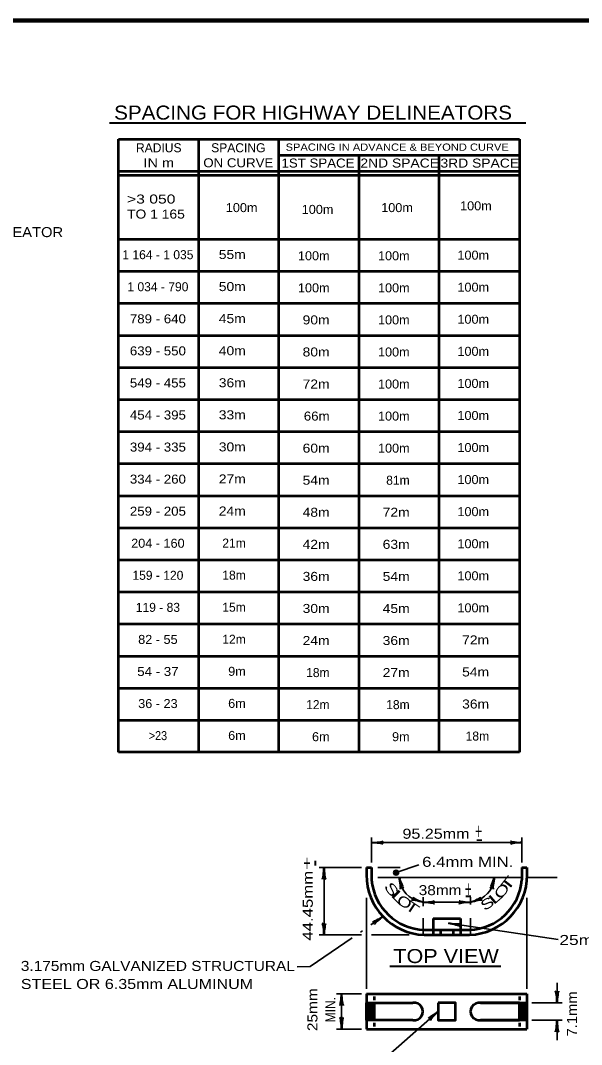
# Model space of a CAD drawing. Extents: x -89 to 766, y -60 to 484.
# Drawn here: x 393.7 to 561.6, y 171.5 to 478.1 of the extents above; entities that cross this region are included whole.
import ezdxf
from ezdxf.enums import TextEntityAlignment as Align

# ---------------------------------------------------------------- set-up
doc = ezdxf.new("R2010")
doc.units = 0
doc.header["$LTSCALE"] = 1.1
doc.linetypes.add('MEDIUM_DASHED', pattern=[4.5, 3, -1.5])
doc.layers.add('1', color=7, linetype='Continuous', lineweight=35)

msp = doc.modelspace()

# ---------------------------------------------------------------- hatches: boundary and pattern name
at = {"layer": '1'}
msp.add_hatch(color=256, dxfattribs=at).paths.add_polyline_path([(506.875, 222.927, 1), (505.375, 222.927, 1)])

# ---------------------------------------------------------------- linework, layer by layer
at = {"layer": '1', "lineweight": 40}
for p, q in [((420.336, 447.477), (545.003, 447.477)), ((504.235, 194.956), (537.477, 194.956))]:
    msp.add_line(p, q, dxfattribs=at)
at = {"layer": '1', "lineweight": 53}
for p, q in [((423.047, 258.995), (423.047, 442.595)), ((423.047, 442.595), (543.047, 442.595)), ((447.047, 258.995), (447.047, 442.595)), ((471.047, 258.995), (471.047, 442.595)), ((543.047, 442.595), (543.047, 258.995)), ((471.047, 437.795), (543.047, 437.795)), ((495.047, 258.995), (495.047, 437.795)), ((519.047, 258.995), (519.047, 437.795)), ((423.047, 432.995), (543.047, 432.995)), ((423.047, 431.795), (543.047, 431.795)), ((423.047, 412.595), (543.047, 412.595)), ((423.047, 402.995), (543.047, 402.995)), ((423.047, 393.395), (543.047, 393.395)), ((423.047, 383.795), (543.047, 383.795)), ((423.047, 374.195), (543.047, 374.195)), ((423.047, 364.595), (543.047, 364.595)), ((423.047, 354.995), (543.047, 354.995)), ((423.047, 345.395), (543.047, 345.395)), ((423.047, 335.795), (543.047, 335.795)), ((423.047, 326.195), (543.047, 326.195)), ((423.047, 316.595), (543.047, 316.595)), ((423.047, 306.995), (543.047, 306.995)), ((423.047, 297.395), (543.047, 297.395)), ((423.047, 287.795), (543.047, 287.795)), ((423.047, 278.195), (543.047, 278.195)), ((423.047, 268.595), (543.047, 268.595)), ((543.047, 258.995), (423.047, 258.995)), ((497.317, 224.421), (497.317, 222.294)), ((497.317, 224.421), (498.817, 224.421)), ((498.817, 224.421), (498.817, 220.794)), ((543.817, 224.421), (543.817, 220.794)), ((543.817, 224.421), (545.317, 224.421)), ((545.317, 224.421), (545.317, 222.294)), ((517.192, 209.169), (517.192, 204.294)), ((517.192, 209.169), (525.442, 209.169)), ((525.442, 209.169), (525.442, 204.294)), ((514.567, 205.794), (528.067, 205.794)), ((514.567, 204.294), (528.067, 204.294)), ((497.317, 186.593), (545.317, 186.593)), ((497.317, 186.593), (497.317, 183.968)), ((499.567, 185.843), (499.567, 184.718)), ((543.067, 185.843), (543.067, 184.718)), ((545.317, 186.593), (545.317, 183.968)), ((497.317, 183.546), (497.738, 183.968)), ((497.317, 182.485), (498.799, 183.968)), ((497.317, 181.425), (499.567, 183.675)), ((497.317, 180.364), (499.567, 182.614)), ((497.317, 179.303), (499.567, 181.553)), ((499.567, 183.968), (499.567, 178.718)), ((499.567, 183.968), (511.192, 183.968)), ((499.567, 183.968), (499.567, 178.718)), ((543.067, 178.718), (543.067, 183.968)), ((543.067, 183.968), (543.067, 178.718)), ((545.317, 181.345), (543.067, 183.595)), ((545.317, 180.284), (543.067, 182.534)), ((545.317, 179.223), (543.067, 181.473)), ((545.317, 182.405), (543.754, 183.968)), ((545.317, 183.466), (544.815, 183.968)), ((497.317, 178.718), (497.317, 176.093)), ((511.192, 178.718), (497.317, 178.718)), ((497.792, 178.718), (499.567, 180.493)), ((498.852, 178.718), (499.567, 179.432)), ((499.567, 177.968), (499.567, 176.843)), ((544.762, 178.718), (543.067, 180.413)), ((543.701, 178.718), (543.067, 179.352)), ((543.067, 177.968), (543.067, 176.843)), ((545.317, 178.718), (545.317, 176.093)), ((497.317, 176.093), (545.317, 176.093))]:
    msp.add_line(p, q, dxfattribs=at)
at = {"layer": '1'}
for p, q in [((498.817, 225.921), (498.817, 233.421)), ((543.817, 225.921), (543.817, 233.421)), ((498.817, 231.921), (543.817, 231.921)), ((495.817, 224.421), (483.067, 224.421)), ((484.567, 224.421), (484.567, 204.294)), ((500.692, 224.468), (507.357, 224.468)), ((506.126, 222.927), (512.985, 225.24)), ((500.692, 221.468), (543.817, 221.468)), ((545.359, 221.468), (554.359, 221.468)), ((497.317, 215.421), (497.317, 188.093)), ((514.192, 215.544), (514.192, 212.889)), ((528.442, 215.544), (528.442, 213.382)), ((545.317, 215.421), (545.317, 188.093)), ((514.192, 214.044), (528.442, 214.044)), ((502.225, 209.781), (498.552, 207.251)), ((514.192, 209.258), (514.192, 206.169)), ((528.442, 209.258), (528.442, 206.169)), ((496.081, 205.549), (495.493, 205.144)), ((521.85, 207.763), (554.609, 202.879)), ((493.023, 203.443), (480.455, 194.787)), ((495.817, 204.294), (483.067, 204.294)), ((510.067, 204.294), (498.817, 204.294)), ((514.192, 205.419), (514.192, 204.669)), ((528.442, 205.419), (528.442, 204.669)), ((480.455, 194.787), (476.517, 194.736)), ((554.317, 189.968), (554.317, 183.968)), ((495.817, 186.593), (488.317, 186.593)), ((489.817, 186.593), (489.817, 176.093)), ((546.817, 183.968), (555.817, 183.968)), ((546.817, 178.718), (555.817, 178.718)), ((554.317, 178.718), (554.317, 172.718)), ((495.817, 176.093), (488.317, 176.093))]:
    msp.add_line(p, q, dxfattribs=at)
at = {"layer": '1', "linetype": 'MEDIUM_DASHED', "lineweight": 53}
for p, q in [((519.442, 205.794), (519.442, 204.294)), ((523.192, 205.794), (523.192, 204.294))]:
    msp.add_line(p, q, dxfattribs=at)
at = {"layer": '1', "lineweight": 158}
msp.add_lwpolyline([(759.817, 478.083), (-31.883, 477.983), (-31.783, -48.017)], dxfattribs=at)
at = {"layer": '1'}
msp.add_lwpolyline([(518.692, 181.343), (504.481, 168.773), (493.885, 168.773)], dxfattribs=at)
at = {"layer": '1', "lineweight": 53}
for points in [[(497.317, 178.718), (497.317, 183.968), (511.192, 183.968)], [(511.192, 178.718), (499.567, 178.718), (499.567, 183.968)], [(531.442, 183.968), (545.317, 183.968), (545.317, 178.718), (531.442, 178.718)], [(531.442, 178.718), (543.067, 178.718), (543.067, 183.968), (531.442, 183.968)]]:
    msp.add_lwpolyline(points, dxfattribs=at)
msp.add_lwpolyline([(518.692, 183.968), (518.692, 178.718), (523.942, 178.718), (523.942, 183.968)], close=True, dxfattribs=at)
at = {"layer": '1'}
msp.add_circle((506.125, 222.927), 0.75, dxfattribs=at)
at = {"layer": '1', "lineweight": 53}
for centre, radius, start, end in [((515.106, 222.129), 17.844, 179.46942, 268.10829), ((515.106, 222.129), 16.344, 184.68607, 268.10829), ((527.527, 222.129), 16.344, 271.89171, 355.31393), ((527.527, 222.129), 17.844, 271.89171, 0.53058), ((511.543, 181.343), 2.648, 262.37185, 97.62815), ((511.543, 181.343), 2.648, 262.37185, 97.62815), ((531.09, 181.343), 2.648, 82.37185, 277.62815), ((531.09, 181.343), 2.648, 82.37185, 277.62815)]:
    msp.add_arc(centre, radius, start, end, dxfattribs=at)
at = {"layer": '1'}
for centre, start, end in [((515.106, 222.129), 198.64913, 263.51251), ((527.527, 222.129), 276.48749, 341.85662)]:
    msp.add_arc(centre, 8.094, start, end, dxfattribs=at)
at = {"layer": '1', "lineweight": 40}
for centre, major_axis, ratio, start_param, end_param in [((500.161, 231.667), (-2.108, 0.211), 0.07063, 3.1407148, 5.41811), ((500.126, 232.253), (-2.143, -0.187), 0.122415, 0.8963533, 3.1415927), ((542.507, 231.59), (2.143, 0.187), 0.122415, 0.8963533, 3.1415927), ((542.507, 231.59), (2.143, 0.187), 0.122415, 0.8963533, 3.1415927), ((542.472, 232.175), (2.108, -0.211), 0.07063, 3.1407148, 5.41811), ((542.472, 232.175), (2.108, -0.211), 0.07063, 3.1407148, 5.41811), ((484.313, 223.077), (0.211, 2.108), 0.07063, 3.1407148, 5.41811), ((484.313, 223.077), (0.211, 2.108), 0.07063, 3.1407148, 5.41811), ((484.898, 223.112), (-0.187, 2.143), 0.122415, 0.8963533, 3.1415927), ((484.898, 223.112), (-0.187, 2.143), 0.122415, 0.8963533, 3.1415927), ((507.062, 220.109), (-0.362, 2.12), 0.122415, 3.1415927, 5.386832), ((507.638, 220.223), (0.738, -1.985), 0.07063, 4.006668, 6.2840632), ((534.996, 220.223), (-0.738, -1.985), 0.07063, 6.2823074, 8.5597026), ((535.571, 220.109), (0.362, 2.12), 0.122415, 0.8963533, 3.1415927), ((512.821, 214.25), (2.071, -0.443), 0.07063, 0.8650754, 3.1424706), ((513.033, 214.796), (1.983, -0.833), 0.122415, 3.1415927, 5.386832), ((529.6, 214.796), (-1.983, -0.833), 0.122415, 0.8963533, 3.1415927), ((529.813, 214.25), (-2.071, -0.443), 0.07063, 3.1407148, 5.41811), ((515.536, 213.79), (-2.108, 0.211), 0.07063, 3.1407148, 5.41811), ((515.536, 213.79), (-2.108, 0.211), 0.07063, 3.1407148, 5.41811), ((515.501, 214.375), (-2.143, -0.187), 0.122415, 0.8963533, 3.1415927), ((515.501, 214.375), (-2.143, -0.187), 0.122415, 0.8963533, 3.1415927), ((527.132, 213.712), (2.143, 0.187), 0.122415, 0.8963533, 3.1415927), ((527.132, 213.712), (2.143, 0.187), 0.122415, 0.8963533, 3.1415927), ((527.097, 214.298), (2.108, -0.211), 0.07063, 3.1407148, 5.41811), ((527.097, 214.298), (2.108, -0.211), 0.07063, 3.1407148, 5.41811), ((500.973, 209.227), (1.855, 1.022), 0.07063, 3.1407148, 5.41811), ((500.973, 209.227), (1.855, 1.022), 0.07063, 3.1407148, 5.41811), ((501.334, 208.765), (1.658, 1.37), 0.122415, 0.8963533, 3.1415927), ((501.334, 208.765), (1.658, 1.37), 0.122415, 0.8963533, 3.1415927), ((484.235, 205.603), (0.187, -2.143), 0.122415, 0.8963533, 3.1415927), ((484.235, 205.603), (0.187, -2.143), 0.122415, 0.8963533, 3.1415927), ((484.821, 205.638), (-0.211, -2.108), 0.07063, 3.1407148, 5.41811), ((484.821, 205.638), (-0.211, -2.108), 0.07063, 3.1407148, 5.41811), ((523.143, 207.314), (-2.054, 0.519), 0.07063, 3.1407148, 5.41811), ((523.194, 207.898), (-2.147, 0.131), 0.122415, 0.8963533, 3.1415927), ((553.985, 185.277), (0.187, -2.143), 0.122415, 0.8963533, 3.1415927), ((554.571, 185.312), (-0.211, -2.108), 0.07063, 3.1407148, 5.41811), ((489.563, 185.248), (0.211, 2.108), 0.07063, 3.1407148, 5.41811), ((489.563, 185.248), (0.211, 2.108), 0.07063, 3.1407148, 5.41811), ((490.148, 185.283), (-0.187, 2.143), 0.122415, 0.8963533, 3.1415927), ((490.148, 185.283), (-0.187, 2.143), 0.122415, 0.8963533, 3.1415927), ((517.516, 180.642), (-1.718, -1.239), 0.07063, 6.2823074, 8.5597026), ((517.516, 180.642), (-1.718, -1.239), 0.07063, 6.2823074, 8.5597026), ((517.931, 180.227), (1.481, 1.56), 0.122415, 0.8963533, 3.1415927), ((517.931, 180.227), (1.481, 1.56), 0.122415, 0.8963533, 3.1415927), ((489.485, 177.402), (0.187, -2.143), 0.122415, 0.8963533, 3.1415927), ((490.071, 177.437), (-0.211, -2.108), 0.07063, 3.1407148, 5.41811), ((554.063, 177.373), (0.211, 2.108), 0.07063, 3.1407148, 5.41811), ((554.648, 177.408), (-0.187, 2.143), 0.122415, 0.8963533, 3.1415927)]:
    msp.add_ellipse(centre, major_axis=major_axis, ratio=ratio, start_param=start_param, end_param=end_param, dxfattribs=at)

# ---------------------------------------------------------------- texts
at = {"layer": '1'}
for s, height, width, p in [('SPACING FOR HIGHWAY DELINEATORS', 4.2, 1.1, (421.724, 448.403)), ('SPACING IN ADVANCE & BEYOND CURVE', 2.16, 1.15, (473.057, 439.084)), ('1ST SPACE', 2.7, 1.1, (471.826, 434.051)), ('2ND SPACE', 2.7, 1.15, (495.441, 434.051)), ('3RD SPACE', 2.7, 1.15, (519.418, 434.036)), ('>3 050', 2.7, 1.3, (425.582, 423.27)), ('100m', 2.7, 1.05, (455.159, 420.706)), ('100m', 2.7, 1.05, (501.679, 420.706)), ('100m', 2.7, 1.05, (525.294, 421.238)), ('TO 1 165', 2.7, 1.15, (425.582, 418.77)), ('100m', 2.7, 1.05, (477.886, 420.173)), ('HOUSED DELINEATOR', 3, 1.1, (358.152, 413.22)), ('95.25mm', 3, 1.2, (508.048, 233.078)), ('+', 4.8, 0.55, (529.826, 232.976)), ('+', 4.8, 0.55, (478.435, 223.433)), ('6.4mm MIN.', 3, 1.25, (513.94, 224.667)), ('38mm', 3, 1.15, (512.904, 216.188)), ('+', 4.8, 0.55, (526.72, 215.666)), ('25mm FLAT', 3, 1.3, (555.001, 201.268)), ('TOP VIEW', 4.2, 1.15, (505.31, 195.853)), ('3.175mm GALVANIZED STRUCTURAL', 3, 1.15, (393.792, 193.494)), ('STEEL OR 6.35mm ALUMINUM', 3, 1.2, (393.792, 188.094))]:
    msp.add_text(s, height=height, dxfattribs=dict(at, width=width)).set_placement(p)
for s, p in [('RADIUS', (435.081, 438.627)), ('SPACING', (458.897, 438.627)), ('1 164 - 1 035', (434.825, 406.606)), ('1 034 - 790', (434.825, 397.006)), ('159 - 120', (434.825, 310.606)), ('119 - 83', (434.825, 301.006))]:
    msp.add_text(s, height=2.7, dxfattribs=at).set_placement(p, align=Align.CENTER)
for s, width, p in [('IN m', 1.2, (435.081, 434.127)), ('ON CURVE', 1.1, (458.897, 434.127)), ('789 - 640', 1.1, (434.825, 387.406)), ('639 - 550', 1.1, (434.825, 377.805)), ('549 - 455', 1.1, (434.825, 368.206)), ('454 - 395', 1.1, (434.825, 358.606)), ('394 - 335', 1.1, (434.825, 349.006)), ('334 - 260', 1.1, (434.825, 339.406)), ('259 - 205', 1.1, (434.825, 329.805)), ('204 - 160', 1.05, (434.825, 320.206)), ('82 - 55', 1.05, (434.825, 291.406)), ('54 - 37', 1.1, (434.825, 281.805)), ('36 - 23', 1.05, (434.825, 272.206)), ('>23', 0.9, (434.825, 262.606))]:
    msp.add_text(s, height=2.7, dxfattribs=dict(at, width=width)).set_placement(p, align=Align.CENTER)
for s, width, p in [('55m', 1.15, (461.129, 406.658)), ('100m', 1.05, (486.229, 406.281)), ('100m', 1.05, (510.197, 406.281)), ('100m', 1.05, (533.977, 406.469)), ('50m', 1.15, (461.129, 397.058)), ('100m', 1.05, (486.229, 396.68)), ('100m', 1.05, (510.197, 396.68)), ('100m', 1.05, (533.977, 396.869)), ('45m', 1.15, (461.129, 387.458)), ('90m', 1.15, (486.229, 387.081)), ('100m', 1.05, (510.197, 387.081)), ('100m', 1.05, (533.977, 387.269)), ('40m', 1.15, (461.129, 377.858)), ('80m', 1.15, (486.229, 377.481)), ('100m', 1.05, (510.197, 377.481)), ('100m', 1.05, (533.977, 377.669)), ('36m', 1.15, (461.129, 368.258)), ('72m', 1.15, (486.229, 367.881)), ('100m', 1.05, (510.197, 367.881)), ('100m', 1.05, (533.977, 368.069)), ('33m', 1.15, (461.129, 358.658)), ('66m', 1.1, (486.229, 358.281)), ('100m', 1.05, (510.197, 358.281)), ('100m', 1.05, (533.977, 358.469)), ('30m', 1.15, (461.129, 349.058)), ('60m', 1.15, (486.229, 348.68)), ('100m', 1.05, (510.197, 348.68)), ('100m', 1.05, (533.977, 348.869)), ('27m', 1.15, (461.129, 339.458)), ('54m', 1.15, (486.229, 339.081)), ('100m', 1.05, (533.977, 339.269)), ('24m', 1.15, (461.129, 329.858)), ('48m', 1.15, (486.229, 329.481)), ('72m', 1.15, (510.197, 329.481)), ('100m', 1.05, (533.977, 329.669)), ('42m', 1.15, (486.229, 319.881)), ('63m', 1.15, (510.197, 319.881)), ('100m', 1.05, (533.977, 320.069)), ('36m', 1.15, (486.229, 310.281)), ('54m', 1.15, (510.197, 310.281)), ('100m', 1.05, (533.977, 310.469)), ('100m', 1.05, (533.977, 300.869)), ('30m', 1.15, (486.229, 300.68)), ('45m', 1.15, (510.197, 300.68)), ('24m', 1.15, (486.229, 291.081)), ('36m', 1.15, (510.197, 291.081)), ('72m', 1.15, (533.977, 291.269)), ('9m', 1.05, (461.129, 281.858)), ('27m', 1.15, (510.197, 281.481)), ('54m', 1.15, (533.977, 281.669)), ('6m', 1.05, (461.129, 272.258)), ('36m', 1.15, (533.977, 272.069)), ('6m', 1.05, (461.129, 262.658)), ('6m', 1.05, (486.229, 262.281)), ('9m', 1.05, (510.197, 262.281))]:
    msp.add_text(s, height=2.7, dxfattribs=dict(at, width=width)).set_placement(p, align=Align.RIGHT)
for s, p in [('81m', (510.197, 339.081)), ('21m', (461.129, 320.258)), ('18m', (461.129, 310.658)), ('15m', (461.129, 301.058)), ('12m', (461.129, 291.458)), ('18m', (486.229, 281.481)), ('12m', (486.229, 271.881)), ('18m', (510.197, 271.881)), ('18m', (533.977, 262.469))]:
    msp.add_text(s, height=2.7, dxfattribs=at).set_placement(p, align=Align.RIGHT)
for p in [(530.005, 230.824), (526.718, 213.96)]:
    msp.add_text('-', height=4.8, dxfattribs=at).set_placement(p)
msp.add_text('-', height=4.8, rotation=90, dxfattribs=at).set_placement((483.813, 224.689))
for s, rotation, width, p in [('44.45mm', 90, 1.25, (481.192, 202.567)), ('T', 51.983, 1.8, (539.398, 216.995)), ('S', 306.861, 1.6, (502.314, 218.727)), ('L', 315.068, 2.1, (504.26, 216.154)), ('O', 51.629, 1.5, (537.474, 214.688)), ('O', 325.945, 1.4, (506, 214.098)), ('T', 326.299, 1.65, (508.445, 212.353)), ('S', 32.545, 1.45, (532.581, 211.361)), ('L', 40.753, 1.9, (535.294, 213.107)), ('7.1mm', 90, 1.1, (560.303, 173.88))]:
    msp.add_text(s, height=3, rotation=rotation, dxfattribs=dict(at, width=width)).set_placement(p)
for s, width, p in [('25mm', 1.15, (482.588, 181.898)), ('MIN.', 0.9, (487.988, 181.898))]:
    msp.add_text(s, height=3, rotation=90, dxfattribs=dict(at, width=width)).set_placement(p, align=Align.CENTER)

doc.saveas('drawing.dxf')
